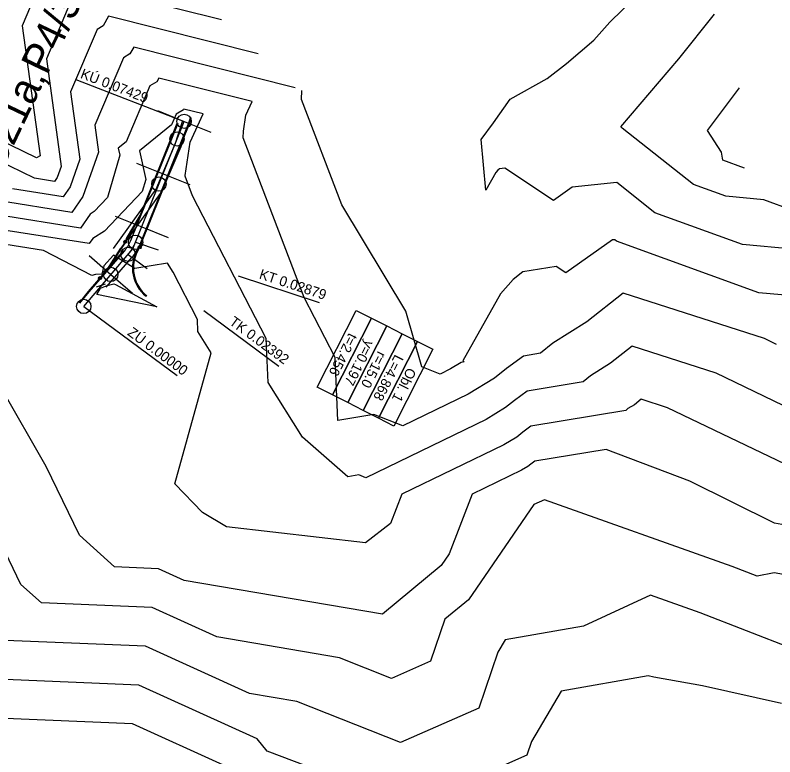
# Model space of a CAD drawing. Extents: x -549394 to -546608, y -1037055 to -1033629.
# Drawn here: x -548467.8 to -548202.8, y -1034181.6 to -1033923 of the extents above; entities that cross this region are included whole.
import ezdxf

# ---------------------------------------------------------------- set-up
doc = ezdxf.new("R2010")
doc.units = 0
for name, color, linetype in [('HLAVNI_VRST', 7, 'Continuous'), ('HRANA_L', 7, 'Continuous'), ('NORM_VRST', 7, 'Continuous'), ('POLYGONY_SITUACE_PO', 7, 'Continuous'), ('u_sirka_5m', 7, 'Continuous'), ('x_navrh_C21a', 7, 'Continuous'), ('x_osa_C21a', 7, 'Continuous'), ('x_popis_oblouky_C21a', 7, 'Continuous'), ('x_popis_pricne_rezy_C21a', 7, 'Continuous'), ('x_popis_velky_C21a', 7, 'Continuous')]:
    doc.layers.add(name, color=color, linetype=linetype)

msp = doc.modelspace()

# ---------------------------------------------------------------- linework, layer by layer
at = {"layer": 'HLAVNI_VRST'}
for p, q in [((-548260.394045, -1033925.450674), (-548247.64875, -1033912.85875)), ((-548435.254609, -1033923.340472), (-548437.166173, -1033926.737679)), ((-548383.04, -1033936.453846), (-548435.254609, -1033923.340472)), ((-548437.166173, -1033926.737679), (-548439.22772, -1033927.970729)), ((-548266.031967, -1033931.696885), (-548260.394045, -1033925.450674)), ((-548439.22772, -1033927.970729), (-548448.499641, -1033949.744648)), ((-548275.565303, -1033939.795152), (-548266.031967, -1033931.696885)), ((-548282.263267, -1033945.103762), (-548275.565303, -1033939.795152)), ((-548295.203333, -1033952.317524), (-548282.263267, -1033945.103762)), ((-548448.499641, -1033949.744648), (-548445.262643, -1033973.197508)), ((-548301.01, -1033960.486667), (-548295.203333, -1033952.317524)), ((-548305.283143, -1033966.317429), (-548301.01, -1033960.486667)), ((-548303.6049, -1033984.0048), (-548305.283143, -1033966.317429)), ((-548445.262643, -1033973.197508), (-548448.702058, -1033982.89045)), ((-548299.417029, -1033977.0128), (-548300.135329, -1033977.813713)), ((-548298.878333, -1033976.590345), (-548299.417029, -1033977.0128)), ((-548297.024514, -1033976.284097), (-548298.878333, -1033976.590345)), ((-548280.023646, -1033987.57099), (-548297.024514, -1033976.284097)), ((-548300.135329, -1033977.813713), (-548303.6049, -1033984.0048)), ((-548257.948966, -1033981.373103), (-548273.497151, -1033982.970988)), ((-548244.654432, -1033991.915227), (-548257.948966, -1033981.373103)), ((-548451.078973, -1033986.353764), (-548468.798144, -1033983.549941)), ((-548448.702058, -1033982.89045), (-548451.078973, -1033986.353764)), ((-548273.497151, -1033982.970988), (-548280.023646, -1033987.57099)), ((-548214.153333, -1034002.961754), (-548244.654432, -1033991.915227)), ((-548178.505228, -1034006.284721), (-548214.153333, -1034002.961754)), ((-548457.036154, -1034080.402051), (-548472.695765, -1034052.912118)), ((-548261.657703, -1034074.403784), (-548286.60758, -1034078.506119)), ((-548232.478908, -1034085.461765), (-548261.657703, -1034074.403784)), ((-548445.444305, -1034104.383576), (-548457.036154, -1034080.402051)), ((-548289.01098, -1034080.350392), (-548291.199571, -1034081.689415)), ((-548288.006099, -1034079.553049), (-548289.01098, -1034080.350392)), ((-548286.60758, -1034078.506119), (-548288.006099, -1034079.553049)), ((-548291.199571, -1034081.689415), (-548308.44229, -1034090.015115)), ((-548202.963659, -1034100.188415), (-548232.478908, -1034085.461765)), ((-548308.44229, -1034090.015115), (-548316.426604, -1034110.829623)), ((-548175.359777, -1034105.017593), (-548202.963659, -1034100.188415)), ((-548433.152143, -1034115.396429), (-548445.444305, -1034104.383576)), ((-548316.426604, -1034110.829623), (-548319.243631, -1034114.922626)), ((-548319.243631, -1034114.922626), (-548339.7, -1034131.87)), ((-548417.822553, -1034116.032804), (-548433.152143, -1034115.396429)), ((-548408.835319, -1034120.113404), (-548417.822553, -1034116.032804)), ((-548339.7, -1034131.87), (-548408.835319, -1034120.113404)), ((-548339.7, -1034131.87), (-548339.7, -1034131.87)), ((-548339.7, -1034131.87), (-548339.7, -1034131.87)), ((-548339.7, -1034131.87), (-548339.7, -1034131.87)), ((-548339.7, -1034131.87), (-548339.7, -1034131.87)), ((-548339.7, -1034131.87), (-548339.7, -1034131.87))]:
    msp.add_line(p, q, dxfattribs=at)
at = {"layer": 'HRANA_L'}
for p, q in [((-548406.68, -1033958.51), (-548410.09, -1033968.88)), ((-548409.45, -1033959.86), (-548412.29, -1033968.4)), ((-548418.68, -1033983.64), (-548412.29, -1033968.4)), ((-548410.09, -1033968.88), (-548416.68, -1033984.37)), ((-548433.6, -1034004.34), (-548418.68, -1033983.64)), ((-548416.68, -1033984.37), (-548431.43, -1034004.97)), ((-548436.45, -1034016.83), (-548439.54, -1034017.88))]:
    msp.add_line(p, q, dxfattribs=at)
at = {"layer": 'NORM_VRST'}
for p, q in [((-548457.609028, -1033908.285994), (-548465.433343, -1033926.660394)), ((-548395.871776, -1033924.644357), (-548444.019826, -1033912.552273)), ((-548448.418374, -1033918.128361), (-548456.966492, -1033938.202521)), ((-548236.306446, -1033938.183802), (-548223.870541, -1033922.623108)), ((-548465.433343, -1033926.660394), (-548459.175552, -1033971.99965)), ((-548460.372733, -1033972.734961), (-548540.43962, -1033933.768609)), ((-548426.489391, -1033934.128671), (-548427.814586, -1033936.48379)), ((-548370.208224, -1033948.263336), (-548426.489391, -1033934.128671)), ((-548427.814586, -1033936.48379), (-548430.037065, -1033937.813097)), ((-548456.966492, -1033938.202521), (-548451.791171, -1033975.699009)), ((-548430.037065, -1033937.813097), (-548440.03279, -1033961.286775)), ((-548256.578636, -1033961.860455), (-548236.306446, -1033938.183802)), ((-548461.14866, -1033979.815037), (-548535.895494, -1033943.437808)), ((-548417.724174, -1033944.91687), (-548418.462999, -1033946.2299)), ((-548385.179452, -1033953.090274), (-548417.724174, -1033944.91687)), ((-548420.846411, -1033947.655464), (-548429.12414, -1033967.09465)), ((-548418.462999, -1033946.2299), (-548420.846411, -1033947.655464)), ((-548367.931974, -1033952.325837), (-548367.899231, -1033949.275769)), ((-548226.319583, -1033963.169167), (-548215.118, -1033948.308632)), ((-548387.369714, -1033957.854143), (-548385.179452, -1033953.090274)), ((-548353.919149, -1033989.11), (-548367.931974, -1033952.325837)), ((-548409.111413, -1033955.976011), (-548411.655757, -1033957.497832)), ((-548408.958957, -1033955.705068), (-548409.111413, -1033955.976011)), ((-548402.243379, -1033957.391644), (-548408.958957, -1033955.705068)), ((-548411.655757, -1033957.497832), (-548413.257898, -1033961.260255)), ((-548406.788762, -1033967.277952), (-548402.243379, -1033957.391644)), ((-548388.233478, -1033963.426377), (-548387.369714, -1033957.854143)), ((-548440.03279, -1033961.286775), (-548438.734114, -1033970.696006)), ((-548413.257898, -1033961.260255), (-548424.516127, -1033970.265704)), ((-548388.258155, -1033965.724979), (-548388.233478, -1033963.426377)), ((-548256.10918, -1033962.33082), (-548256.578636, -1033961.860455)), ((-548231.249129, -1033982.044015), (-548256.10918, -1033962.33082)), ((-548221.410267, -1033970.797067), (-548226.319583, -1033963.169167)), ((-548367.012903, -1034021.494516), (-548388.258155, -1033965.724979)), ((-548429.12414, -1033967.09465), (-548431.917535, -1033969.329085)), ((-548431.917535, -1033969.329085), (-548431.369017, -1033971.808786)), ((-548408.581304, -1033978.841836), (-548406.788762, -1033967.277952)), ((-548459.175552, -1033971.99965), (-548460.372733, -1033972.734961)), ((-548438.734114, -1033970.696006), (-548444.245466, -1033986.228071)), ((-548431.369017, -1033971.808786), (-548435.594872, -1033986.57641)), ((-548424.516127, -1033970.265704), (-548422.305434, -1033980.259653)), ((-548220.920423, -1033973.546338), (-548221.410267, -1033970.797067)), ((-548213.400746, -1033976.27806), (-548220.920423, -1033973.546338)), ((-548451.791171, -1033975.699009), (-548453.15865, -1033979.55283)), ((-548454.103688, -1033980.92981), (-548461.14866, -1033979.815037)), ((-548453.15865, -1033979.55283), (-548454.103688, -1033980.92981)), ((-548408.584335, -1033979.12412), (-548408.581304, -1033978.841836)), ((-548405.975269, -1033985.973011), (-548408.584335, -1033979.12412)), ((-548422.305434, -1033980.259653), (-548423.512821, -1033984.478974)), ((-548219.931111, -1033986.143041), (-548231.249129, -1033982.044015)), ((-548423.512821, -1033984.478974), (-548436.728889, -1033998.324856)), ((-548448.054259, -1033991.777719), (-548476.447629, -1033987.284845)), ((-548444.245466, -1033986.228071), (-548448.054259, -1033991.777719)), ((-548435.594872, -1033986.57641), (-548440.284444, -1033991.489465)), ((-548380.245548, -1034035.701355), (-548405.975269, -1033985.973011)), ((-548206.703198, -1033987.376091), (-548219.931111, -1033986.143041)), ((-548194.236567, -1033991.904925), (-548206.703198, -1033987.376091)), ((-548331.5625, -1034026.155), (-548353.919149, -1033989.11)), ((-548445.029544, -1033997.201673), (-548484.097113, -1033991.01975)), ((-548441.715581, -1033992.373023), (-548445.029544, -1033997.201673)), ((-548440.284444, -1033991.489465), (-548441.715581, -1033992.373023)), ((-548442.004829, -1034002.625627), (-548491.746598, -1033994.754654)), ((-548457.928562, -1034005.051242), (-548499.396082, -1033998.489558)), ((-548436.728889, -1033998.324856), (-548440.762093, -1034000.814884)), ((-548440.762093, -1034000.814884), (-548442.004829, -1034002.625627)), ((-548259.433198, -1034001.360523), (-548275.700729, -1034012.826198)), ((-548258.692808, -1034001.284433), (-548259.433198, -1034001.360523)), ((-548258.059735, -1034001.786439), (-548258.692808, -1034001.284433)), ((-548208.375556, -1034019.780468), (-548258.059735, -1034001.786439)), ((-548441.139333, -1034013.752), (-548457.928562, -1034005.051242)), ((-548433.534737, -1034006.702105), (-548436.942941, -1034010.435294)), ((-548431.917869, -1034007.747705), (-548433.534737, -1034006.702105)), ((-548426.078889, -1034011.372963), (-548431.917869, -1034007.747705)), ((-548436.942941, -1034010.435294), (-548437.654407, -1034013.303729)), ((-548414.708085, -1034009.516383), (-548426.078889, -1034011.372963)), ((-548412.775484, -1034012.611935), (-548414.708085, -1034009.516383)), ((-548279.100903, -1034010.568819), (-548290.711667, -1034012.486897)), ((-548275.700729, -1034012.826198), (-548279.100903, -1034010.568819)), ((-548439.78375, -1034013.38), (-548441.139333, -1034013.752)), ((-548437.654407, -1034013.303729), (-548439.78375, -1034013.38)), ((-548404.248774, -1034029.091677), (-548412.775484, -1034012.611935)), ((-548290.711667, -1034012.486897), (-548294.0856, -1034015.1328)), ((-548435.710756, -1034017.291429), (-548433.447119, -1034016.635254)), ((-548433.447119, -1034016.635254), (-548432.833793, -1034016.851034)), ((-548432.833793, -1034016.851034), (-548418.450435, -1034024.691014)), ((-548294.0856, -1034015.1328), (-548298.584431, -1034020.149042)), ((-548439.338519, -1034020.401481), (-548438.045806, -1034018.236129)), ((-548438.045806, -1034018.236129), (-548435.710756, -1034017.291429)), ((-548431.82, -1034019.72), (-548431.82, -1034019.72)), ((-548431.82, -1034019.72), (-548431.82, -1034019.72)), ((-548431.82, -1034019.72), (-548431.82, -1034019.72)), ((-548431.82, -1034019.72), (-548431.82, -1034019.72)), ((-548431.82, -1034019.72), (-548431.82, -1034019.72)), ((-548431.82, -1034019.72), (-548431.82, -1034019.72)), ((-548418.450435, -1034024.691014), (-548439.338519, -1034020.401481)), ((-548356.242323, -1034042.311032), (-548367.012903, -1034021.494516)), ((-548298.584431, -1034020.149042), (-548311.666866, -1034043.493284)), ((-548255.749062, -1034019.87868), (-548268.407383, -1034029.960093)), ((-548206.453194, -1034035.789696), (-548255.749062, -1034019.87868)), ((-548183.09331, -1034022.137172), (-548208.375556, -1034019.780468)), ((-548325.960851, -1034045.652128), (-548331.5625, -1034026.155)), ((-548404.067533, -1034033.339648), (-548404.248774, -1034029.091677)), ((-548268.407383, -1034029.960093), (-548280.31433, -1034037.367113)), ((-548399.418571, -1034040.700672), (-548404.067533, -1034033.339648)), ((-548379.587357, -1034051.128194), (-548380.245548, -1034035.701355)), ((-548280.31433, -1034037.367113), (-548284.565241, -1034040.875448)), ((-548202.249633, -1034037.809862), (-548206.453194, -1034035.789696)), ((-548412.194959, -1034086.410909), (-548399.418571, -1034040.700672)), ((-548284.565241, -1034040.875448), (-548290.525388, -1034041.855434)), ((-548252.611232, -1034038.403607), (-548260.123894, -1034044.386885)), ((-548223.354335, -1034047.84673), (-548252.611232, -1034038.403607)), ((-548355.303133, -1034064.323976), (-548356.242323, -1034042.311032)), ((-548311.666866, -1034043.493284), (-548311.190889, -1034043.925778)), ((-548290.525388, -1034041.855434), (-548296.387265, -1034046.243632)), ((-548319.601673, -1034048.124382), (-548325.960851, -1034045.652128)), ((-548312.203519, -1034044.067222), (-548315.963704, -1034046.367778)), ((-548311.190889, -1034043.925778), (-548312.203519, -1034044.067222)), ((-548296.387265, -1034046.243632), (-548300.599216, -1034049.585686)), ((-548260.123894, -1034044.386885), (-548267.190619, -1034048.782921)), ((-548315.963704, -1034046.367778), (-548319.601673, -1034048.124382)), ((-548267.190619, -1034048.782921), (-548269.713517, -1034050.865103)), ((-548194.423945, -1034061.750229), (-548223.354335, -1034047.84673)), ((-548367.59, -1034070.124444), (-548379.587357, -1034051.128194)), ((-548300.599216, -1034049.585686), (-548309.772671, -1034055.198187)), ((-548269.713517, -1034050.865103), (-548289.219452, -1034054.072329)), ((-548289.219452, -1034054.072329), (-548293.593543, -1034057.346771)), ((-548309.772671, -1034055.198187), (-548332.557849, -1034066.20008)), ((-548293.593543, -1034057.346771), (-548296.736471, -1034059.840588)), ((-548251.840405, -1034058.813676), (-548254.066907, -1034060.198729)), ((-548249.473402, -1034056.928534), (-548251.840405, -1034058.813676)), ((-548240.255475, -1034059.903764), (-548249.473402, -1034056.928534)), ((-548296.736471, -1034059.840588), (-548303.581637, -1034064.028596)), ((-548254.861793, -1034060.854759), (-548287.913516, -1034066.289224)), ((-548254.066907, -1034060.198729), (-548254.861793, -1034060.854759)), ((-548186.598257, -1034085.690596), (-548240.255475, -1034059.903764)), ((-548342.736471, -1034062.242941), (-548355.303133, -1034064.323976)), ((-548303.581637, -1034064.028596), (-548345.514024, -1034084.275777)), ((-548332.557849, -1034066.20008), (-548342.736471, -1034062.242941)), ((-548287.913516, -1034066.289224), (-548290.799821, -1034068.44991)), ((-548292.873725, -1034070.09549), (-548297.390604, -1034072.859006)), ((-548290.799821, -1034068.44991), (-548292.873725, -1034070.09549)), ((-548351.812727, -1034083.950909), (-548367.59, -1034070.124444)), ((-548297.390604, -1034072.859006), (-548332.976641, -1034090.041832)), ((-548347.981569, -1034083.316471), (-548351.812727, -1034083.950909)), ((-548345.514024, -1034084.275777), (-548347.981569, -1034083.316471)), ((-548465.868146, -1034121.489536), (-548483.218324, -1034085.595027)), ((-548402.530783, -1034096.37487), (-548412.194959, -1034086.410909)), ((-548332.976641, -1034090.041832), (-548336.901282, -1034100.273077)), ((-548286.852055, -1034093.677945), (-548309.690559, -1034126.861173)), ((-548283.162113, -1034091.987324), (-548286.852055, -1034093.677945)), ((-548217.675497, -1034115.221637), (-548283.162113, -1034091.987324)), ((-548394.1, -1034101.426667), (-548402.530783, -1034096.37487)), ((-548345.628571, -1034106.983095), (-548394.1, -1034101.426667)), ((-548336.901282, -1034100.273077), (-548345.628571, -1034106.983095)), ((-548209.03193, -1034118.592281), (-548217.675497, -1034115.221637)), ((-548203.11795, -1034117.469665), (-548209.03193, -1034118.592281)), ((-548164.086824, -1034124.29799), (-548203.11795, -1034117.469665)), ((-548458.65539, -1034127.951623), (-548465.868146, -1034121.489536)), ((-548246.197324, -1034125.276056), (-548269.620435, -1034136.007826)), ((-548228.862632, -1034131.426316), (-548246.197324, -1034125.276056)), ((-548420.099149, -1034129.552203), (-548458.65539, -1034127.951623)), ((-548309.690559, -1034126.861173), (-548317.897605, -1034133.660419)), ((-548397.494894, -1034139.815532), (-548420.099149, -1034129.552203)), ((-548317.897605, -1034133.660419), (-548322.91988, -1034148.255542)), ((-548195.523158, -1034144.427368), (-548228.862632, -1034131.426316)), ((-548269.620435, -1034136.007826), (-548296.869417, -1034140.772767)), ((-548422.375745, -1034143.071602), (-548484.158636, -1034140.506818)), ((-548354.646768, -1034147.101939), (-548397.494894, -1034139.815532)), ((-548296.869417, -1034140.772767), (-548299.43, -1034145.142)), ((-548386.154468, -1034159.51766), (-548422.375745, -1034143.071602)), ((-548299.43, -1034145.142), (-548306.139759, -1034164.641084)), ((-548336.569249, -1034154.279201), (-548354.646768, -1034147.101939)), ((-548322.91988, -1034148.255542), (-548336.569249, -1034154.279201)), ((-548424.65234, -1034156.591001), (-548487.739898, -1034153.972057)), ((-548247.054088, -1034153.38146), (-548277.413107, -1034158.690243)), ((-548244.991374, -1034153.80229), (-548247.054088, -1034153.38146)), ((-548228.120609, -1034156.866261), (-548244.991374, -1034153.80229)), ((-548383.379149, -1034175.330851), (-548424.65234, -1034156.591001)), ((-548200.536316, -1034163.039649), (-548228.120609, -1034156.866261)), ((-548369.593536, -1034162.333878), (-548386.154468, -1034159.51766)), ((-548277.413107, -1034158.690243), (-548287.73303, -1034176.299576)), ((-548333.438499, -1034176.688402), (-548369.593536, -1034162.333878)), ((-548306.139759, -1034164.641084), (-548333.438499, -1034176.688402)), ((-548426.928936, -1034170.110401), (-548475.446619, -1034168.096293)), ((-548395.18766, -1034184.52234), (-548426.928936, -1034170.110401)), ((-548379.901471, -1034179.714989), (-548383.379149, -1034175.330851)), ((-548287.73303, -1034176.299576), (-548289.359639, -1034181.026627)), ((-548366.124133, -1034184.877533), (-548379.901471, -1034179.714989)), ((-548289.359639, -1034181.026627), (-548330.307748, -1034199.097603))]:
    msp.add_line(p, q, dxfattribs=at)
at = {"layer": 'POLYGONY_SITUACE_PO'}
for centre in [(-548408.9, -1033960.005), (-548425.84807, -1034002.167516), (-548428.43151, -1034006.398255), (-548434.495976, -1034013.394132), (-548443.912857, -1034024.557031)]:
    msp.add_circle(centre, 2.5, dxfattribs=at)
at = {"layer": 'u_sirka_5m'}
for centre, radius in [((-548411.379354, -1033966.173006), 2.5), ((-548417.699566, -1033981.896097), 2.5), ((-548429.476389, -1034001.993916), 0.5), ((-548424.445889, -1034003.942015), 0.5), ((-548438.250324, -1034014.671728), 0.5)]:
    msp.add_circle(centre, radius, dxfattribs=at)
at = {"layer": 'x_navrh_C21a'}
for p, q in [((-548427.471799, -1034001.514825), (-548411.02553, -1033960.600663)), ((-548424.224341, -1034002.820206), (-548406.774471, -1033959.409338)), ((-548428.968096, -1034000.893637), (-548424.243789, -1033992.81405)), ((-548428.742946, -1034001.003862), (-548424.018689, -1033992.924361)), ((-548442.284171, -1034019.325112), (-548429.942741, -1034005.088224)), ((-548442.084037, -1034019.475912), (-548429.753837, -1034005.251978)), ((-548435.892998, -1034011.899843), (-548430.989932, -1034004.204671)), ((-548435.682134, -1034012.034142), (-548430.789031, -1034004.354607)), ((-548436.063324, -1034017.873895), (-548427.109182, -1034007.544531)), ((-548445.441505, -1034023.267366), (-548442.284171, -1034019.325112)), ((-548445.250447, -1034023.428601), (-548442.084037, -1034019.475912))]:
    msp.add_line(p, q, dxfattribs=at)
for points in [[(-548424.243789, -1033992.81405), (-548411.329177, -1033960.685757)], [(-548423.99238, -1034002.913448), (-548406.470824, -1033959.324243)]]:
    msp.add_lwpolyline(points, dxfattribs=at)
for centre, radius, start, end in [((-548439.765745, -1033996.573027), 11.63, 318.98904698, 338.1915003), ((-548439.765745, -1033996.573027), 11.88, 319.0791982, 338.10134908), ((-548439.765745, -1033996.573027), 13.25, 319.0791982, 338.10134908), ((-548439.765745, -1033996.573027), 16.75, 319.0791982, 338.10134908), ((-548439.765745, -1033996.573027), 17, 329.03628896, 338.10134908), ((-548414.427943, -1034011.186659), 12.5, 150.02570934, 231.70907894), ((-548414.104651, -1034011.124942), 12.5, 150.44325912, 231.38086021)]:
    msp.add_arc(centre, radius, start, end, dxfattribs=at)
at = {"layer": 'x_osa_C21a'}
msp.add_lwpolyline([(-548443.912857, -1034024.55703), (-548426.785378, -1034004.499302), (-548408.9, -1033960.005)], dxfattribs=at)
msp.add_arc((-548439.765745, -1033996.573027), 15, 319.0791982, 338.10134908, dxfattribs=at)
at = {"layer": 'x_popis_oblouky_C21a'}
for points in [[(-548446.731225, -1033945.447935), (-548408.9, -1033960.005)], [(-548425.84807, -1034002.167516), (-548417.934593, -1034004.759739)], [(-548428.43151, -1034006.398255), (-548421.827806, -1034011.288391)], [(-548390.100228, -1034013.877461), (-548361.801807, -1034023.147193)], [(-548443.912857, -1034024.557031), (-548411.336905, -1034048.679987)], [(-548402.054828, -1034025.930563), (-548375.854866, -1034045.332008)]]:
    msp.add_lwpolyline(points, dxfattribs=at)
for points in [[(-548343.534915, -1034028.643702), (-548357.107325, -1034055.397948), (-548362.458174, -1034052.683466), (-548348.885765, -1034025.92922)], [(-548338.184066, -1034031.358184), (-548351.756476, -1034058.11243), (-548357.107325, -1034055.397948), (-548343.534915, -1034028.643702)], [(-548332.833217, -1034034.072666), (-548346.405626, -1034060.826912), (-548351.756476, -1034058.11243), (-548338.184066, -1034031.358184)], [(-548327.482368, -1034036.787148), (-548341.054777, -1034063.541394), (-548346.405626, -1034060.826912), (-548332.833217, -1034034.072666)], [(-548322.131518, -1034039.50163), (-548335.703928, -1034066.255876), (-548341.054777, -1034063.541394), (-548327.482368, -1034036.787148)]]:
    msp.add_lwpolyline(points, close=True, dxfattribs=at)
at = {"layer": 'x_popis_pricne_rezy_C21a'}
for points in [[(-548418.17845, -1033956.275341), (-548408.9, -1033960.005), (-548399.62155, -1033963.734659)], [(-548425.518358, -1033974.535176), (-548416.239908, -1033978.264836), (-548406.961457, -1033981.994495)], [(-548432.977677, -1033993.092077), (-548423.699226, -1033996.821737), (-548414.420776, -1034000.551396)], [(-548442.052133, -1034006.84398), (-548434.495976, -1034013.394132), (-548426.939819, -1034019.944284)]]:
    msp.add_lwpolyline(points, dxfattribs=at)

# ---------------------------------------------------------------- texts
at = {"layer": 'x_popis_oblouky_C21a'}
for s, rotation, p in [('KÚ 0.07429', 338.95379001, (-548445.34958, -1033944.778635)), ('KT 0.02879', 341.86272167, (-548382.989765, -1034014.759694)), ('TK 0.02392', 323.47952586, (-548393.428147, -1034030.559924)), ('ZÚ 0.00000', 323.47952586, (-548428.940274, -1034034.296629)), ('t=2.456', 243.12322887, (-548351.408438, -1034033.568469)), ('y=0.197', 243.12322887, (-548345.53272, -1034036.026234)), ('r=15.0', 243.12322887, (-548341.261301, -1034039.893039)), ('L=4.868', 243.12322887, (-548335.325083, -1034041.073815)), ('Obl. 1', 243.12322887, (-548330.896779, -1034045.608563))]:
    msp.add_text(s, height=3.5, rotation=rotation, dxfattribs=at).set_placement(p)
at = {"layer": 'x_popis_velky_C21a'}
msp.add_text('C21a,P4/30', height=10.5, rotation=64.473381, dxfattribs=at).set_placement((-548472.859288, -1033978.068494))

doc.saveas('drawing.dxf')
